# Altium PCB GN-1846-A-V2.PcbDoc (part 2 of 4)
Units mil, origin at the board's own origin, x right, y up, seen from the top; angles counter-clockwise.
Board outline 11624.17 x 2384.02 mil, 4 copper layers (Top, GND, VCC, Bottom), stack 40.7 mil thick; 450 components, 346 nets, 1652 pads, 832 vias.
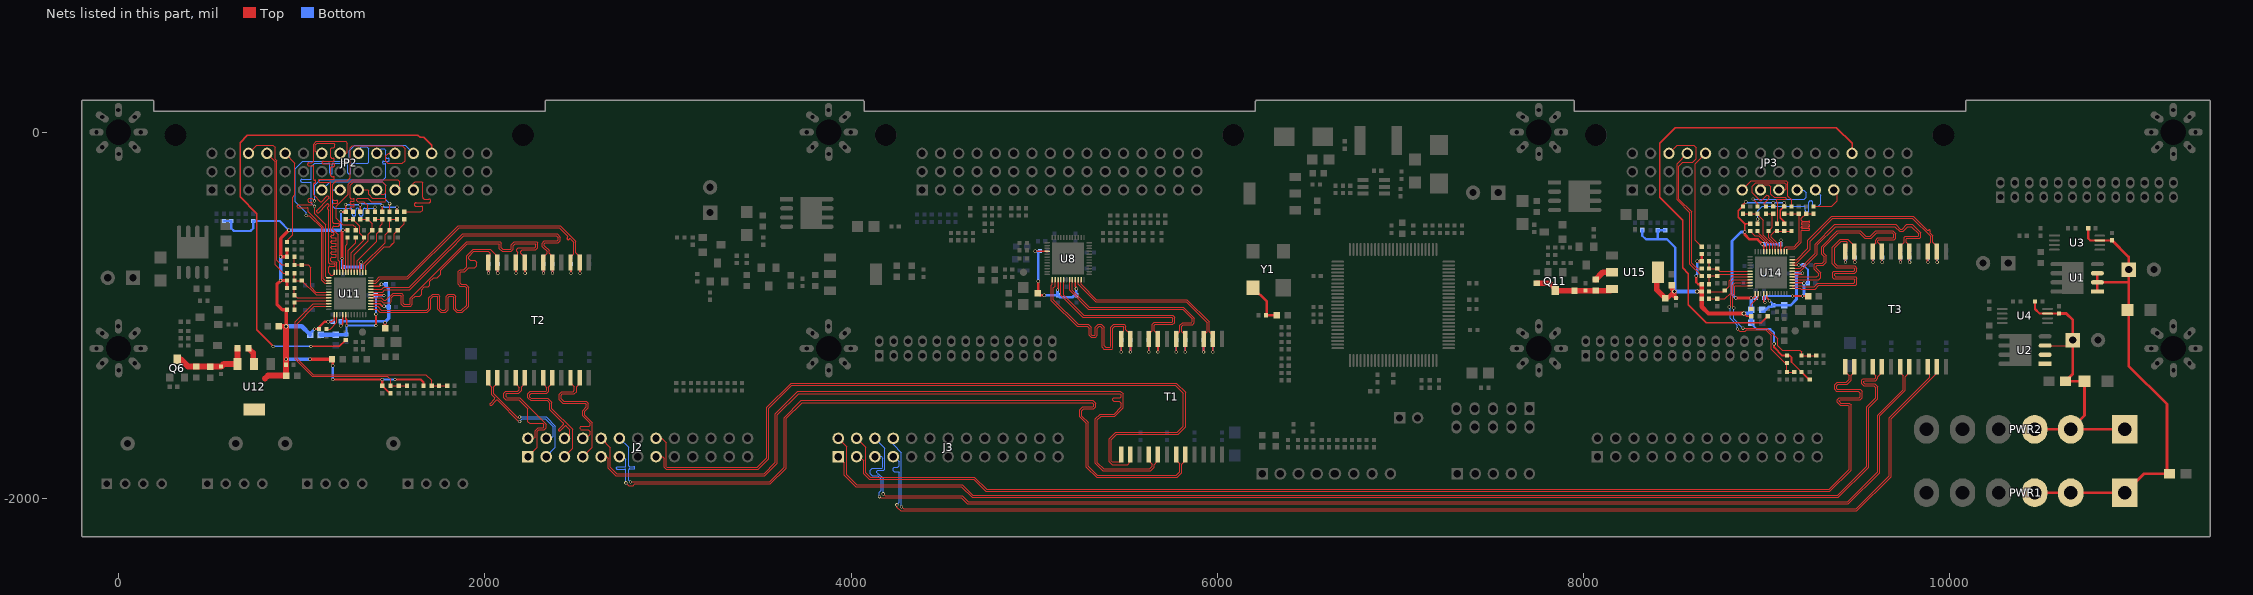
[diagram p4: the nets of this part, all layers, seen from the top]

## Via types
v1: diameter 18, hole 12, Top to Bottom, 768 vias
v2: diameter 24, hole 16, Top to Bottom, 34 vias
v3: diameter 30, hole 20, Top to Bottom, 27 vias
v4: diameter 40, hole 30, Top to Bottom, 2 vias
v5: diameter 24, hole 14, Top to Bottom, 1 vias

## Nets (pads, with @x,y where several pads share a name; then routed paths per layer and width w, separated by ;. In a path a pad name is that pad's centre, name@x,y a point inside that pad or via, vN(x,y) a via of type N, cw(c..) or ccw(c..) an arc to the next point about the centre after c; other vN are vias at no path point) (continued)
A_MX2_N: J2.12 T1.19 | length 4235.9
  Top w6: v1(2795,-1910) 3555,-1910 3635,-1830 3635,-1558 3728,-1465 5320,-1465 5335,-1480 5335,-1500 5325,-1510 5270,-1510 5260,-1520 5260,-1550 5295,-1585 5295,-1824.44 5344.56,-1874 5775,-1874 5795,-1854 5795,-1810 T1.19@5775,-1790
  Bottom w6: J2.12@2735,-1671.65 2785,-1721.65 2785,-1820.6 ccw(c2790.4,-1820.6) 2790.4,-1826 2813.98,-1826 cw(c2813.98,-1831.4) 2819.38,-1831.4 2819.38,-1832.6 cw(c2813.98,-1832.6) 2813.98,-1838 2790.4,-1838 ccw(c2790.4,-1843.4) 2785,-1843.4 2785,-1900 v1(2795,-1910)
A_MX2_P: J2.11 T1.20 | length 4225.8
  Top w6: v1(2770,-1915) 2785,-1930 2810,-1930 2819,-1921 3559.56,-1921 3646,-1834.56 3646,-1562.56 3732.56,-1476 5315.44,-1476 5324,-1484.56 5324,-1495.44 5320.44,-1499 5265.44,-1499 5249,-1515.44 5249,-1554.56 5284,-1589.56 5284,-1829 5340,-1885 5779.56,-1885 5806,-1858.56 5806,-1814 T1.20@5825,-1795
  Bottom w6: J2.11@2735,-1771.65 2756.65,-1771.65 2770,-1785 2770,-1822.6 cw(c2764.6,-1822.6) 2764.6,-1828 2723.6,-1828 ccw(c2723.6,-1833.4) 2718.2,-1833.4 2718.2,-1834.6 ccw(c2723.6,-1834.6) 2723.6,-1840 2764.6,-1840 cw(c2764.6,-1845.4) 2770,-1845.4 v1(2770,-1915)
A_MX3_N: J2.10 T1.16 | length 4210.2
  Top w6: J2.10@2635,-1671.65 2685.91,-1722.56 2685.91,-1830.35 2720.56,-1865 3525,-1865 3587,-1803 3587,-1538 3710,-1415 5470.56,-1415 5485,-1429.44 5485,-1505 5440,-1550 5365,-1550 5345,-1570 5345,-1804.44 5379.56,-1839 5630.28,-1839 5644.28,-1825 5644.28,-1814.28 5625,-1795 T1.16@5625,-1759.96
A_MX3_P: J2.9 T1.17 | length 4202.5
  Top w6: J2.9@2635,-1771.65 2665.65,-1771.65 2674,-1780 2674,-1834 2716,-1876 3529.56,-1876 3598,-1807.56 3598,-1542.56 3712.78,-1427.78 5467.78,-1427.78 5474,-1434 5474,-1445 5469,-1450 5435,-1450 5430,-1455 5430,-1465 5435,-1470 5465,-1470 5474,-1479 5474,-1500.44 5435.56,-1538.89 ; 5435.44,-1539 5360.44,-1539 5334,-1565.44 5334,-1809 5375,-1850 5634.83,-1850 5655.28,-1829.56 5655.28,-1814.72 5675,-1795 T1.17@5675,-1790
A_MX4_N: J2.16 T1.13 | length 4227.9
  Top w6: J2.16@2935,-1671.65 2966.65,-1671.65 2991,-1696 2991,-1826 2995,-1830 3488,-1830 3540,-1778 3540,-1502 3672,-1370 5775.56,-1370 5826,-1420.44 5826,-1609.56 5785.56,-1650 5450.4,-1650 5421,-1679.4 5421,-1795.44 5425.56,-1800 5470,-1800 5475,-1795 T1.13@5475,-1769.96
A_MX4_P: J2.15 T1.14 | length 4235
  Top w6: J2.15@2935,-1771.65 2971.65,-1771.65 2980,-1780 2980,-1830.56 2990.44,-1841 3492.56,-1841 3551,-1782.56 3551,-1506.56 3676.56,-1381 5771,-1381 5815,-1425 5815,-1605 5781,-1639 5445.84,-1639 5410,-1674.84 5410,-1800 5425,-1815 5510,-1815 5525,-1800 T1.14@5525,-1769.96
  Top w8: T1.14@5526.14,-1770.8 T1.14@5526.14,-1741.14
A_TD1_N: C52.2 T1.3 U8.10 | length 1102.9
  Top w6: U8.10@5240.12,-804.96 5240.12,-830.12 5335,-925 5829.44,-925 5944.72,-1040.28 5944.72,-1090.28 5926.14,-1108.86 5926.14,-1140.88 5926.14,-1190.88
  Top w8: T1.3@5926.14,-1140.88 T1.3@5928.15,-1142.89
  Top w10: v1(5925,-1200) T1.3@5925,-1140.04
  Bottom w10: v1(5925,-1200) C52.2@5925,-1135
A_TD1_P: C53.2 T1.2 U8.11 | length 1054
  Top w6: U8.11@5255.87,-804.96 5255.87,-830.31 5339.56,-914 5834,-914 5955.72,-1035.72 5955.72,-1090.72 5976.14,-1111.14 T1.2@5976.14,-1140.88
  Top w8: T1.2@5976.14,-1140.88 T1.2@5978.15,-1142.89 ; T1.2@5976.14,-1111.14 T1.2@5976.14,-1108.83
  Top w10: v1(5975,-1200) T1.2@5975,-1140.04
  Bottom w10: v1(5975,-1200) C53.2@5975,-1135
A_TD2_N: C51.2 T1.6 U8.7 | length 1105.6
  Top w6: U8.7@5192.87,-804.96 5192.87,-863.43 5295.44,-966 5810.44,-966 5864,-1019.56 5864,-1036 5860,-1040 5810.44,-1040 5795,-1055.44 5795,-1090 T1.6@5775,-1110
  Top w10: v1(5775,-1200) T1.6@5775,-1110
  Bottom w10: v1(5775,-1200) C51.2@5775,-1135
A_TD2_P: C46.2 T1.5 U8.8 | length 1104.8
  Top w6: U8.8@5208.62,-804.96 5208.62,-863.62 5300,-955 5815,-955 5875,-1015 5875,-1040.56 5864.56,-1051 5815,-1051 5806,-1060 5806,-1091 T1.5@5825,-1110
  Top w10: v1(5825,-1200) T1.5@5825,-1110
  Bottom w6: v1(5825,-1200) v1@5826.14,-1201.14
  Bottom w10: v1(5825,-1200) C46.2@5825,-1135
A_TD3_N: C45.2 T1.9 U8.4 | length 1111.5
  Top w6: U8.4@5145.63,-804.96 5145.63,-891.19 5265.44,-1011 5751,-1011 5755,-1015 5755,-1035 5751,-1039 5655.44,-1039 5645,-1049.44 5645,-1085 T1.9@5626.14,-1103.86 ; T1.9@5625,-1105 T1.9@5626.14,-1103.86 ; T1.9@5626.14,-1140.88 T1.9@5626.14,-1103.86
  Top w8: T1.9@5626.14,-1140.88 T1.9@5628.15,-1142.89
  Top w10: v1(5625,-1200) T1.9@5625,-1140.04
  Bottom w10: v1(5625,-1200) C45.2@5625,-1135
A_TD3_P: C50.2 T1.8 U8.5 | length 1104.3
  Top w6: U8.5@5161.38,-804.96 5161.38,-891.38 5270,-1000 5755.56,-1000 5766,-1010.44 5766,-1039.56 5755.56,-1050 5660,-1050 5656,-1054 5656,-1085 T1.8@5675,-1104
  Top w10: v1(5675,-1200) T1.8@5675,-1104
  Bottom w10: v1(5675,-1200) C50.2@5675,-1135
A_TD4_N: C48.2 T1.12 U8.1 | length 1092.7
  Top w6: U8.1@5098.39,-804.96 5098.39,-831.61 5094,-836 5094,-919.56 5235.44,-1061 5290,-1061 5300,-1071 5300,-1110 5310,-1120 5335,-1120 5345,-1110 5345,-1070 5354,-1061 5361,-1061 5370,-1070 5370,-1175 5380,-1185 5425,-1185 5430,-1180 5430,-1070 5439,-1061 5486,-1061 5490,-1065 5490,-1085 5475,-1100 T1.12@5475,-1130.04
  Top w10: v1(5475,-1200) T1.12@5475,-1140.04
  Bottom w10: v1(5475,-1200) C48.2@5475,-1135
A_TD4_P: C49.2 T1.11 U8.2 | length 1103
  Top w6: U8.2@5114.13,-804.96 5114.13,-840.87 5105,-850 5105,-915 5240,-1050 5294.56,-1050 5311,-1066.44 5311,-1105 5315,-1109 5330.44,-1109 5334,-1105.44 5334,-1065.44 5349.44,-1050 5365.56,-1050 5381,-1065.44 5381,-1165 5390,-1174 5415,-1174 5419,-1170 5419,-1065.44 5434.44,-1050 5490.56,-1050 5501,-1060.44 5501,-1080 5525,-1104 T1.11@5525,-1130.04
  Top w8: T1.11@5526.14,-1130.04 T1.11@5526.14,-1118.83
  Top w10: v1(5525,-1200) T1.11@5525,-1140.04
  Bottom w10: v1(5525,-1200) C49.2@5525,-1135
APHY105: B4.1 C35.1 C36.1 C37.1 U8.3 U8.9 U8.40 | length 711.2
  Top w8: v1(5126.85,-861.48) 5129.88,-858.45 5129.88,-848.45 U8.3@5129.88,-804.96 ; U8.9@5224.37,-804.96 5224.37,-841.68 5230,-847.31 v1(5230,-855)
  Top w10: v1(5005,-650) 5069.41,-650 U8.40@5070.04,-650.63
  Top w15: B4.1@5020,-880.47 B4.1@5021.85,-878.62 ; v1(5021.85,-814.16) B4.1@5021.85,-878.62 ; v1(5055,-890) 5033.23,-890 B4.1@5021.85,-878.62
  Bottom w12: v1(5005,-650) 5021.85,-650 v1(5021.85,-814.16)
  Bottom w15: v1(5055,-890) C37.1@5130,-890 ; v1(5126.85,-861.48) 5126.85,-886.85 C37.1@5130,-890 ; v1(5230,-855) C36.1@5230,-890 ; C36.1@5230.84,-889.16 C36.1@5230,-890 ; C37.1@5130,-890 5140.66,-900.66 5209.34,-900.66 5220,-890 C36.1@5230,-890
B3V3A: B8.1 C75.1 C76.1 C77.1 U11.6 U11.41 | length 693.8
  Top w8: U11.41@1239.53,-995.8 1239.53,-1020 1245,-1025.47 v1(1245,-1055)
  Top w10: U11.6@1378.11,-888.71 1449.53,-888.71 v1(1449.53,-891.58)
  Top w12: v1(1405,-1055) v1(1405,-993.71)
  Bottom w12: C76.1@1245,-1095.47 v1(1245,-1055) v1(1405,-1055) ; v1(1405,-993.71) C75.1@1405,-891.58 ; v1(1449.53,-891.58) C75.1@1405,-891.58 ; C75.1@1405,-891.58 1404.53,-891.58 C75.1@1404.53,-890 1405,-890 C75.1@1405,-891.58
  Bottom w18: C77.1@1169.53,-1105.47 C76.1@1245,-1105.47
  Bottom w24: B8.1@1104.53,-1105 C77.1@1174.53,-1105
B3V3D: B6.2 B8.2 C65.1 C66.1 C67.1 C68.1 C89.1 C90.1 R94.1 R97.1 R102.1 R106.2 R107.1 R108.2 R110.2 R112.2 R113.2 R114.2 R119.2 R123.2 R124.2 R128.2 R131.2 R412.2 R413.2 R414.2 U11.15 U11.21 U11.37 U12.2 U12.4 | length 4425.3
  Top w8: v1(1145,-1035) 1165,-1035 1176.54,-1023.46 U11.37@1176.54,-995.8 ; U11.21@1223.78,-765.88 v1@1223.78,-693.78 ; R131.2@1240,-435 v1(1240,-395) ; U11.15@1318.27,-765.88 1318.27,-716.73 v1(1325,-710) ; R128.2@1320,-435 v1(1320,-396.5) ; R124.2@1440,-435 v1(1440,-400) ; R119.2@1520,-435 v1(1520,-410)
  Top w10: v1@1220,-540 v1(1225,-535) R106.2@1250,-535 ; R102.1@1440,-1385 R112.2@1480,-1425
  Top w12: v1(1070,-1075) R108.2@1095,-1075 1095,-1065 1125,-1035 v1(1145,-1035) ; B6.2@1165.47,-1240 1170,-1244.53 v1(1170,-1275) ; v1@1175,-1350 v1(1440,-1350) R102.1@1440,-1385 ; v1(1215,-435) R131.2@1240,-435 ; v1(1510,-1350) 1650,-1350 1665,-1365 R97.1@1665,-1385
  Top w15: v1(1220,-690) v1@1220,-540
  Top w18: v2(915,-1060) 915,-975 R110.2@920,-970 895,-970 865,-940 865,-830 v1(885,-810) R114.2@920,-810 R123.2@920,-850 ; R94.1@920,-640 R113.2@920,-680 v1(885,-680) 885,-580 v1(930,-535) ; v1(1045,-1240) B6.2@1165.47,-1240
  Top w24: C90.1@874.53,-1060 v2(915,-1060)
  Top w30: R107.1@710,-1180 735,-1205 U12.2@735,-1270
  Top w32: 800,-1345 815.47,-1329.53 915,-1329.53 C89.1@915,-1270 v1(915,-1240) v2(915,-1060)
  Bottom w8: v1(1240,-395) 1318.5,-395 v1(1320,-396.5) 1324.5,-392 1432,-392 v1(1440,-400) 1450,-410 v1(1520,-410) ; C66.1@1324.53,-735.47 C66.1@1325,-735 v1(1325,-710)
  Bottom w12: R414.2@575,-485 R413.2@615,-485 615,-525 630,-540 720,-540 735,-525 R412.2@735,-485 880,-485 v1(930,-535) ; B8.2@1045.47,-1105 1045.47,-1099.53 v1(1070,-1075) ; v1(1145,-1035) C65.1@1170,-1035 ; v1(1170,-1350) v1(1170,-1275) ; v1(1215,-435) 1215,-525 v1(1225,-535) ; v1(1220,-690) 1220,-730.47 C67.1@1225,-735.47 ; v1(1440,-1350) v1(1510,-1350)
  Bottom w15: C67.1@1225,-735.47 C66.1@1324.53,-735.47
  Bottom w18: v1(885,-810) v1(885,-680) ; v1(915,-1240) v1(1045,-1240) ; v1(930,-535) v1(1225,-535)
  Bottom w24: v2(915,-1060) 1000.47,-1060 B8.2@1045.47,-1105
B5V: C91.1 C92.1 Q6.3 R107.2 R109.1 U12.3 | length 437.2
  Top w32: Q6.3@320,-1240 340,-1240 380,-1280 C91.1@560,-1280 575,-1265 U12.3@649,-1265 649,-1181 R107.2@650,-1180
B_MCLK: JP2.A3 R120.1 | length 855.9
  Top w5: JP2.A3@709.84,-115.13 754.97,-70 842.31,-70 855,-82.69 855,-146.54 865,-156.54 865,-700 890,-725 R120.1@920,-725
B_MDIO: JP2.A4 R122.1 | length 711.8
  Top w5: JP2.A4@809.84,-115.52 855,-160.68 855,-725 900,-770 R122.1@920,-770
B_MX1_N: J2.8 T2.22 | length 693.3
  Top w6: T2.22@2468.15,-1340.8 2468.15,-1368.15 2489.09,-1389.09 2489.09,-1410 2481.49,-1417.6 2419.4,-1417.6 2405,-1432 2405,-1460 2425,-1480 2549.44,-1480 2554,-1484.56 2554,-1500.44 2534,-1520.44 2534,-1549.56 2575,-1590.56 2575,-1600 2570,-1605 2525,-1605 2520,-1610 2520,-1620 2525,-1625 2565,-1625 2575,-1635 2575,-1650 2553.35,-1671.65 J2.8@2535,-1671.65
B_MX1_P: J2.7 T2.23 | length 691.9
  Top w6: T2.23@2518.15,-1340.8 2518.15,-1371.85 2501,-1389 2501,-1416 2488.4,-1428.6 2423.96,-1428.6 2416,-1436.56 2416,-1455.44 2429.56,-1469 2554,-1469 2565,-1480 2565,-1505 2545,-1525 2545,-1545 2586,-1586 2586,-1720.65 J2.7@2535,-1771.65
B_MX2_N: J2.6 T2.19 | length 688.3
  Top w6: T2.19@2318.15,-1340.8 2325,-1347.65 2325,-1380 2339.28,-1394.28 2339.28,-1410 2334.28,-1415 2248,-1415 2235,-1428 2235,-1450.56 2249.44,-1465 2340,-1465 2355,-1480 2355,-1515 2428.75,-1588.75 cw(c2424.94,-1592.57) 2428.75,-1596.39 2403.59,-1621.56 ccw(c2407.4,-1625.38) 2403.59,-1629.2 2404.43,-1630.04 ccw(c2408.25,-1626.23) 2412.07,-1630.04 2437.24,-1604.88 cw(c2441.06,-1608.69) 2444.88,-1604.88 2465,-1625 2465,-1660 2453.35,-1671.65 J2.6@2435,-1671.65
B_MX2_P: J2.5 T2.20 | length 700.6
  Top w6: T2.20@2368.15,-1340.8 2360,-1348.95 2360,-1380 2350.28,-1389.72 2350.28,-1414.56 2338.83,-1426 2252.56,-1426 2246,-1432.56 2246,-1446 2254,-1454 2344.56,-1454 2366,-1475.44 2366,-1509.16 2480,-1623.16 2480,-1726.65 J2.5@2435,-1771.65
B_MX3_N: J2.2 T2.16 | length 685.8
  Top w6: T2.16@2168.15,-1368.15 T2.16@2168.15,-1340.8 2175,-1347.65 2175,-1380 2189.09,-1394.09 2189.09,-1405.91 2180,-1415 2115,-1415 2104,-1426 2104,-1449 2115,-1460 2185,-1460 2235,-1510 2235,-1580 2245,-1590 2315,-1590 2322.5,-1597.5 2322.5,-1611.5 2320,-1614 2290.44,-1614 2275,-1629.44 2275,-1665 2268.35,-1671.65 J2.2@2235,-1671.65
B_MX3_P: J2.1 T2.17 | length 701.7
  Top w6: T2.17@2218.15,-1340.8 2218.15,-1371.85 2201,-1389 2201,-1409.56 2184.56,-1426 2119.56,-1426 2116,-1429.56 2116,-1445 2120,-1449 2189.56,-1449 2335,-1594.44 2335,-1615 2325,-1625 2295,-1625 2286,-1634 2286,-1720.65 J2.1@2235,-1771.65
B_MX4_N: J2.4 T2.13 | length 703.1
  Top w6: T2.13@2018.15,-1340.8 2018.15,-1373.15 2039,-1394 2039,-1434 2053.93,-1448.93 cw(c2050.11,-1452.75) 2053.93,-1456.56 2028.21,-1482.28 ccw(c2032.03,-1486.1) 2028.21,-1489.92 2029.06,-1490.76 ccw(c2032.88,-1486.95) 2036.7,-1490.76 2062.41,-1465.05 cw(c2066.23,-1468.87) 2070.05,-1465.05 2187.5,-1582.5 v1@2190,-1585
  Bottom w6: v1(2190,-1580) 2204,-1566 2330.44,-1566 2374,-1609.56 2374,-1661 2363.35,-1671.65 J2.4@2335,-1671.65
B_MX4_P: J2.3 T2.14 | length 699.8
  Top w6: 2050,-1399.44 2050,-1395 ; T2.14@2068.15,-1340.8 2068.15,-1371.85 2050,-1390 2050,-1395 ; v1(2190,-1555) 2185,-1560 2180.56,-1560 2050,-1429.44 2050,-1395
  Bottom w6: v1(2190,-1555) 2335,-1555 2385,-1605 2385,-1721.65 J2.3@2335,-1771.65
B_TD1_N: C85.2 T2.3 U11.10 | length 1512
  Top w6: U11.10@1378.11,-825.72 1403.27,-825.72 1427.99,-801 1579.56,-801 1859.56,-521 2406,-521 2452.17,-567.17 cw(c2448.35,-570.98) 2452.17,-574.8 2450,-576.97 ccw(c2453.82,-580.79) 2450,-584.61 2450.85,-585.45 ccw(c2454.67,-581.64) 2458.49,-585.45 2460.65,-583.29 cw(c2464.47,-587.11) 2468.29,-583.29 2485,-600 2485,-663.15 T2.3@2468.15,-680
  Top w8: T2.3@2468.15,-680 T2.3@2468.15,-710.88 T2.3@2470,-712.73
  Top w10: v1(2470,-770) T2.3@2470,-712.73
  Bottom w10: v1(2470,-770) C85.2@2470,-720
B_TD1_P: C80.2 T2.2 U11.11 | length 1512
  Top w6: U11.11@1378.11,-809.97 1403.46,-809.97 1423.43,-790 1575,-790 1855,-510 2410.56,-510 2496,-595.44 2496,-657.85 T2.2@2518.15,-680
  Top w8: T2.2@2518.15,-680 T2.2@2518.15,-710.88 T2.2@2520,-712.73
  Top w10: v1(2520,-770) T2.2@2520,-712.73
  Bottom w10: v1(2520,-770) C80.2@2520,-720
B_TD2_N: C83.2 T2.6 U11.7 | length 1494
  Top w6: U11.7@1378.11,-872.97 1442.03,-872.97 1454,-861 1589,-861 1592.03,-857.97 1809,-641 ; 1810,-641 1885,-566 2390,-566 2401,-577 2401,-588 2395,-594 2325.44,-594 2314,-605.44 2314,-624.56 2340,-650.56 2340,-660 T2.6@2318.15,-681.85
  Top w8: T2.6@2318.15,-681.85 T2.6@2318.15,-710.88 T2.6@2320,-712.73
  Top w10: v1(2320,-770) T2.6@2320,-712.73
  Bottom w10: v1(2320,-770) C83.2@2320,-720
B_TD2_P: C84.2 T2.5 U11.8 | length 1510.8
  Top w6: U11.8@1378.11,-857.22 1437.78,-857.22 1448.03,-846.97 1587.47,-846.97 1879.44,-555 2394.56,-555 2412,-572.44 2412,-592.56 2399.56,-605 2330,-605 2325,-610 2325,-620 2351,-646 2351,-661 T2.5@2370,-680
  Top w8: T2.5@2370,-712.73 T2.5@2368.15,-710.88 2370,-709.03 T2.5@2370,-680
  Top w10: v1(2370,-770) T2.5@2370,-712.73
  Bottom w10: v1(2370,-770) C84.2@2370,-720
B_TD3_N: C79.2 T2.9 U11.4 | length 1515.2
  Top w6: U11.4@1378.11,-920.21 1434.65,-920.21 1444.44,-930 1485,-930 1490,-925 1490,-904.56 1503.56,-891 1540.44,-891 1544,-894.56 1544,-939 1555,-950 1595,-950 1604.77,-940.23 ; 1605,-940 1605,-910 1620,-895 1645,-895 1655,-885 1655,-860 1670,-845 1690,-845 1700,-835 1700,-815 1720,-795 1740,-795 1760,-775 1760,-755 1905,-610 2075,-610 2080,-615 2080,-635.56 2094.44,-650 2145,-650 2155,-640 2155,-620 2165,-610 2274,-610 2279,-615 2279,-625.44 2272.8,-631.64 2183.36,-631.64 2175,-640 2175,-650 2180,-655 2180,-670 T2.9@2168.15,-681.85
  Top w10: v1(2170,-770) T2.9@2170,-712.73
  Bottom w10: v1(2170,-770) C79.2@2170,-720
B_TD3_P: C82.2 T2.8 U11.5 | length 1511.6
  Top w6: U11.5@1378.11,-904.46 1434.46,-904.46 1449,-919 1460,-919 1499,-880 1545,-880 1555,-890 1555,-934 1560,-939 1590.44,-939 1594,-935.44 1594,-905.44 1900.44,-599 2084.56,-599 2091,-605.44 2091,-631 2099,-639 2140.44,-639 2144,-635.44 2144,-615.44 2161.35,-598.09 2283.09,-598.09 2290,-605 2290,-630 2277.36,-642.64 2204.6,-642.64 2197.24,-650 ; 2197.64,-650 2197.24,-650 ; T2.8@2218.15,-683.15 2197.24,-662.24 2197.24,-650
  Top w8: T2.8@2218.15,-683.15 T2.8@2218.15,-710.88 T2.8@2220,-712.73
  Top w10: v1(2220,-770) T2.8@2220,-712.73
  Bottom w10: v1(2220,-770) C82.2@2220,-720
B_TD4_N: C81.2 T2.12 U11.1 | length 1522.7
  Top w6: U11.1@1378.11,-967.45 1408.7,-967.45 1425.25,-984 1686.56,-984 1706,-964.56 1706,-909.56 1719.56,-896 1740.44,-896 1744,-899.56 1744,-967.56 1760.44,-984 1786.56,-984 1801,-969.56 1801,-900 1805,-896 1825,-896 1829,-900 1829,-967.56 1845.44,-984 1876.56,-984 1910.91,-949.65 1910.91,-845.44 1894.46,-829 1870,-829 1866,-825 1866,-764.56 1869.56,-761 1889.46,-761 1910.91,-739.56 1945,-739.56 1955,-729.56 1955,-710 1945,-700 1920,-700 1910.91,-690.91 1910.91,-679.09 1940,-650 2020,-650 2030,-660 2030,-683.15
  Top w10: v1(2020,-770) T2.12@2020,-712.73
  Bottom w10: v1(2020,-770) C81.2@2020,-720
B_TD4_P: C78.2 T2.11 U11.2 | length 1517
  Top w6: U11.2@1378.11,-951.71 1414.09,-951.71 1435.38,-973 1682,-973 1695,-960 1695,-905 1715,-885 1745,-885 1755,-895 1755,-963 1765,-973 1782,-973 1790,-965 1790,-895 1800,-885 1829.56,-885 1840,-895.44 1840,-963 1850,-973 1872,-973 1899.91,-945.09 1899.91,-850 1889.91,-840 1864,-840 1855,-831 1855,-760 1865,-750 1884.91,-750 1899.91,-735 1899.91,-674.54 1935.44,-639 2029,-639 2068.15,-678.15 T2.11@2068.15,-710.88
  Top w8: T2.11@2068.15,-710.88 T2.11@2070,-712.73
  Top w10: v1(2070,-770) T2.11@2070,-712.73
  Bottom w10: v1(2070,-770) C78.2@2070,-720
BEPHY_CLK: JP2.A13 R96.1 | length 2753.3
  Top w8: v1(845,-1170) 755,-1080 755,-445 663.15,-353.15 663.15,-56.39 704.04,-15.5 1633.27,-15.5 1646.2,-28.44 1665.75,-28.44 1709.84,-72.53 JP2.A13@1709.84,-115.13 ; v1(1050,-1170) 1205,-1170 R96.1@1240,-1135
  Bottom w8: v1(845,-1170) 890,-1170 ; 915,-1170 890,-1170 ; v1(1050,-1170) 890,-1170
BEPHY_RSTN: JP2.A5 R95.1 | length 524.8
  Top w5: JP2.A5@909.84,-115.13 963.15,-168.44 963.15,-340.85 950,-354 950,-560 920,-590 R95.1@920,-600
BGE0_ENREG: R108.1 U11.38 | length 115.1
  Top w5: R108.1@1135,-1075 1155.86,-1075 1192.28,-1038.58 U11.38@1192.28,-995.8
BGE0_INT_N: R106.1 U11.20 | length 195.2
  Top w5: U11.20@1239.53,-765.88 1239.53,-619.47 1250,-609 R106.1@1250,-575
BGE0_LED0: R103.1 R104.1 R112.1 U11.34 | length 1119.8
  Top w5: U11.34@1148.19,-935.96 1064.04,-935.96 965,-1035 965,-1240 1058.5,-1333.5 1468.5,-1333.5 1485,-1350 R112.1@1485,-1385 R104.1@1575,-1385
BGE0_LED1: R98.1 R99.1 R115.1 U11.35 | length 1302
  Top w5: U11.35@1148.19,-951.71 1068.29,-951.71 975,-1045 975,-1235.86 1062.64,-1323.5 1678.5,-1323.5 1710,-1355 R98.1@1710,-1385 R99.1@1795,-1385
BGE0_LED2: R123.1 R125.1 U11.32 | length 234.2
  Top w5: R123.1@960,-850 R125.1@960,-890 974.46,-904.46 U11.32@1148.19,-904.46
BGE0_PME: R110.1 R111.1 U11.33 | length 232.2
  Top w5: R110.1@960,-970 R111.1@960,-930 969.79,-920.21 U11.33@1148.19,-920.21
BGE0_RXCLK: R87.2 U11.19 | length 207.3
  Top w5: U11.19@1255.28,-765.88 1255.28,-644.72 1295,-605 R87.2@1295,-575
BGE0_RXCTL: R88.2 R116.1 U11.13 | length 421.3
  Top w5: U11.13@1349.76,-765.88 1349.76,-725.24 1449.92,-625.08 1479.92,-625.08 ; 1498.15,-606.85 1479.92,-625.08 ; R88.2@1560,-475 1560,-500 R116.1@1525,-535 1505,-555 1505,-600 1479.92,-625.08
BGE0_RXD0: R89.2 R119.1 R121.1 U11.14 | length 391.3
  Top w5: U11.14@1334.02,-765.88 1334.02,-724.31 1455,-603.33 1455,-560 R121.1@1480,-535 R89.2@1480,-475 R119.1@1520,-475
BGE0_RXD1: R90.2 R124.1 R126.1 U11.16 | length 387.8
  Top w5: U11.16@1302.52,-765.88 1302.52,-702.48 1410,-595 1410,-555 R126.1@1430,-535 1430,-510 1440,-500 R124.1@1440,-475 R90.2@1400,-475
BGE0_RXD2: R91.2 R128.1 R130.1 U11.17 | length 381.9
  Top w5: U11.17@1286.77,-765.88 1286.77,-670.23 1363,-594 1363,-557 R130.1@1385,-535 1385,-500 R91.2@1360,-475 R128.1@1320,-475
BGE0_RXD3: R93.2 R131.1 R132.1 U11.18 | length 384.3
  Top w5: R131.1@1240,-475 R93.2@1280,-475 1318,-513 1318,-553 R132.1@1340,-575 1340,-590 1271.02,-658.98 U11.18@1271.02,-765.88
BMAC_MDC: C93.2 R113.1 R120.2 U11.30 | length 356
  Top w5: R113.1@960,-680 R120.2@960,-725 C93.2@1000,-725 1035,-725 1050,-740 1050,-845 1077.97,-872.97 U11.30@1148.19,-872.97
BMAC_MDIO: C94.2 R114.1 R122.2 U11.31 | length 260.8
  Top w5: R122.2@960,-770 R114.1@960,-810 C94.2@1000,-810 1078.71,-888.71 U11.31@1148.19,-888.71
BPHY105: B7.1 C69.1 C70.1 C71.1 U11.3 U11.9 U11.40 | length 770.2
  Top w8: v1(1213.6,-1056.4) 1223.78,-1046.22 U11.40@1223.78,-995.8 ; U11.3@1378.11,-935.96 1425.96,-935.96 1440,-950 v1(1450,-950) v1@1455,-950
  Top w10: U11.9@1378.11,-841.47 1423.53,-841.47 v1(1435,-830)
  Top w18: v1(1455,-1040) 1455,-1069.53 B7.1@1455.47,-1070
  Bottom w15: v1(1213.6,-1056.4) 1212.56,-1055.36 C69.1@1212.56,-1032.91 1447.91,-1032.91 ; v1(1435,-830) C71.1@1460,-830 1460,-840 1475,-855 C70.1@1475,-950 ; v1(1450,-950) C70.1@1470,-950
  Bottom w18: v1(1455,-1040) 1455,-1035.54 1475,-1015.54 C70.1@1475,-955 C70.1@1470,-950
BRGMII_RXCK: JP2.C11 R87.1 | length 703.1
  Top w5: R87.1@1295,-535 1295,-520 1280,-505 1225,-505 1190,-470 1190,-405 1255,-340 1255,-285 1280,-260 1525,-260 1535,-270 1535,-290.37 JP2.C11@1509.84,-315.52
BRGMII_RXD0: JP2.C7 R89.1 | length 530.6
  Top w5: R89.1@1480,-435 v1(1480,-390)
  Bottom w5: JP2.C7@1109.84,-315.52 1155.37,-270 1440,-270 1460,-290 1460,-370 v1(1480,-390)
BRGMII_RXD1: JP2.C8 R90.1 | length 525.6
  Top w5: R90.1@1400,-435 v1(1400,-410)
  Bottom w5: JP2.C8@1209.84,-315.52 1174.48,-315.52 1170,-320 1170,-405 1180,-415 1265,-415 cw(c1265,-425) 1275,-425 1275,-448 ccw(c1285,-448) 1285,-458 ccw(c1285,-448) 1295,-448 1295,-425 cw(c1305,-425) 1305,-415 cw(c1305,-425) 1315,-425 1315,-448 ccw(c1325,-448) 1325,-458 ccw(c1325,-448) 1335,-448 1335,-425 cw(c1345,-425) 1345,-415 1395,-415 v1(1400,-410)
BRGMII_RXD2: JP2.C9 R91.1 | length 480.1
  Top w5: JP2.C9@1309.84,-315.52 1360.52,-315.52 1365,-320 1365,-340 1385,-360 1455,-360 1460,-365 1460,-375 1455,-380 1380,-380 1360,-360 1305,-360 1300,-365 1300,-375 1305,-380 1340,-380 1360,-400 R91.1@1360,-435
BRGMII_RXD3: JP2.C10 R93.1 | length 541.2
  Top w5: R93.1@1280,-435 1265,-420 1265,-412.75 cw(c1270.25,-412.75) 1270.25,-407.5 1282.75,-407.5 ccw(c1282.75,-402.25) 1288,-402.25 1288,-397.75 ccw(c1282.75,-397.75) 1282.75,-392.5 1270.25,-392.5 cw(c1270.25,-387.25) 1265,-387.25 1265,-382.75 cw(c1270.25,-382.75) 1270.25,-377.5 1282.75,-377.5 ccw(c1282.75,-372.25) 1288,-372.25 1288,-367.75 ccw(c1282.75,-367.75) 1282.75,-362.5 1270.25,-362.5 cw(c1270.25,-357.25) 1265,-357.25 1265,-290 1285,-270 1440,-270 1460,-290 1460,-330 1450,-340 1434.32,-340 JP2.C10@1409.84,-315.52
BRGMII_RXDV: JP2.C12 R88.1 | length 502.3
  Top w5: R88.1@1560,-435 1650,-435 1660,-425 1660,-410 ccw(c1655,-410) 1655,-405 1625,-405 cw(c1625,-395) 1615,-395 cw(c1625,-395) 1625,-385 1695,-385 ccw(c1695,-375) 1705,-375 ccw(c1695,-375) 1695,-365 1670,-365 cw(c1670,-355) 1660,-355 1660,-275 1655,-270 1620,-270 1609.84,-280.16 JP2.C12@1609.84,-315.52
BRGMII_TXCKOUT: JP2.A11 U11.22 | length 1455.4
  Top w5: U11.22@1208.03,-765.88 1208.03,-708.03 1200,-700 1200,-560 1170,-530 1170,-517.75 cw(c1175.25,-517.75) 1175.25,-512.5 1201.19,-512.5 ccw(c1201.19,-507.25) 1206.44,-507.25 1206.44,-502.75 ccw(c1201.19,-502.75) 1201.19,-497.5 1175.25,-497.5 cw(c1175.25,-492.25) 1170,-492.25 1170,-392.75 cw(c1175.25,-392.75) 1175.25,-387.5 1191.19,-387.5 ccw(c1191.19,-382.25) 1196.44,-382.25 1196.44,-377.75 ccw(c1191.19,-377.75) 1191.19,-372.5 1175.25,-372.5 cw(c1175.25,-367.25) 1170,-367.25 1170,-285 1190,-265 1250,-265 1265,-250 1265,-85 1275,-75 1550,-75 1565,-90 1565,-155 1550,-170 1470,-170 1460,-160 1460,-130 1474.48,-115.52 JP2.A11@1509.84,-115.52
BRGMII_TXD0: JP2.A7 U11.23 | length 1465.2
  Top w5: JP2.A7@1109.84,-115.52 1085.52,-115.52 1075,-105 1075,-69.14 1084.14,-60 1175,-60 1180,-65 1180,-80 1175,-85 1165,-85 1160,-90 1160,-137.25 ccw(c1165.25,-137.25) 1165.25,-142.5 1173.27,-142.5 cw(c1173.27,-147.75) 1178.52,-147.75 1178.52,-152.25 cw(c1173.27,-152.25) 1173.27,-157.5 1118.24,-157.5 ccw(c1118.24,-162.75) 1112.99,-162.75 1112.99,-167.25 ccw(c1118.24,-167.25) 1118.24,-172.5 1174.22,-172.5 cw(c1174.22,-177.75) 1179.47,-177.75 1179.47,-182.25 cw(c1174.22,-182.25) 1174.22,-187.5 1165.25,-187.5 ccw(c1165.25,-192.75) 1160,-192.75 1160,-237.25 ccw(c1165.25,-237.25) 1165.25,-242.5 1173.27,-242.5 cw(c1173.27,-247.75) 1178.52,-247.75 1178.52,-252.25 cw(c1173.27,-252.25) 1173.27,-257.5 1096.52,-257.5 1093.4,-260.63 1093.4,-270.1 1095.79,-272.5 1154.75,-272.5 cw(c1154.75,-277.75) 1160,-277.75 1160,-542.25 ccw(c1165.25,-542.25) 1165.25,-547.5 1171.19,-547.5 cw(c1171.19,-552.75) 1176.44,-552.75 1176.44,-557.25 cw(c1171.19,-557.25) 1171.19,-562.5 1165.25,-562.5 ccw(c1165.25,-567.75) 1160,-567.75 1160,-572.25 ccw(c1165.25,-572.25) 1165.25,-577.5 1184.75,-577.5 cw(c1184.75,-582.75) 1190,-582.75 1190,-587.25 cw(c1184.75,-587.25) 1184.75,-592.5 1165.25,-592.5 ccw(c1165.25,-597.75) 1160,-597.75 1160,-602.25 ccw(c1165.25,-602.25) 1165.25,-607.5 1184.75,-607.5 cw(c1184.75,-612.75) 1190,-612.75 1190,-617.25 cw(c1184.75,-617.25) 1184.75,-622.5 1165.25,-622.5 ccw(c1165.25,-627.75) 1160,-627.75 1160,-632.25 ccw(c1165.25,-632.25) 1165.25,-637.5 1184.75,-637.5 cw(c1184.75,-642.75) 1190,-642.75 1190,-647.25 cw(c1184.75,-647.25) 1184.75,-652.5 1165.25,-652.5 ccw(c1165.25,-657.75) 1160,-657.75 1160,-662.25 ccw(c1165.25,-662.25) 1165.25,-667.5 1184.75,-667.5 cw(c1184.75,-672.75) 1190,-672.75 1190,-677.25 cw(c1184.75,-677.25) 1184.75,-682.5 1165.25,-682.5 ccw(c1165.25,-687.75) 1160,-687.75 1160,-702.5 1164.18,-706.68 1186.68,-706.68 1192.28,-712.28 U11.23@1192.28,-765.88
BRGMII_TXD1: JP2.A8 U11.24 | length 1432.9
  Top w5: 1084.72,-438.82 1081.54,-435.63 cw(c1085.25,-431.92) 1081.53,-428.22 1148.46,-361.28 ccw(c1144.75,-357.57) 1148.47,-353.87 1145.28,-350.68 ; 1084.73,-438.83 ccw(c1088.43,-435.1) 1092.13,-438.83 ; 1092.14,-438.82 1137.86,-393.1 cw(c1141.57,-396.81) 1145.27,-393.09 ; 1137.86,-350.68 1109.65,-378.88 cw(c1105.94,-375.17) 1102.23,-378.89 1065,-341.66 1065,-282.75 cw(c1070.25,-282.75) 1070.25,-277.5 1072.75,-277.5 ccw(c1072.75,-272.25) 1078,-272.25 1078,-267.75 ccw(c1072.75,-267.75) 1072.75,-262.5 1070.25,-262.5 cw(c1070.25,-257.25) 1065,-257.25 1065,-185 ccw(c1062.5,-185) 1062.5,-182.5 1037.25,-182.5 cw(c1037.25,-177.25) 1032,-177.25 1032,-172.75 cw(c1037.25,-172.75) 1037.25,-167.5 1055,-167.5 1065,-157.5 1065,-65 1080,-50 1240,-50 1250,-60 1250,-110 1244.48,-115.52 JP2.A8@1209.84,-115.52 ; 1137.87,-350.67 cw(c1141.57,-354.39) 1145.27,-350.67 ; 1141.47,-418.13 1148.34,-425 1148.34,-712.25 ccw(c1153.59,-712.25) 1153.59,-717.5 1177.03,-717.5 cw(c1177.03,-722.75) 1182.28,-722.75 1182.28,-727.25 cw(c1177.03,-727.25) 1177.03,-732.5 1153.59,-732.5 ccw(c1153.59,-737.75) 1148.34,-737.75 1148.34,-768.34 1160,-780 1170,-780 1176.54,-773.46 U11.24@1176.54,-765.88 ; 1141.46,-418.12 cw(c1145.18,-414.42) 1141.46,-410.71 1148.46,-403.71 ccw(c1144.75,-400) 1148.47,-396.29 1145.28,-393.1
BRGMII_TXD2: JP2.A9 U11.25 | length 1458.2
  Top w5: v1(1070,-405) 1070,-445 1130.39,-505.39 1130.39,-789.61 1135,-794.23 U11.25@1148.19,-794.23
  Bottom w5: v1(1070,-405) 1053.5,-388.5 1053.5,-277.75 ccw(c1048.25,-277.75) 1048.25,-272.5 1000.75,-272.5 cw(c1000.75,-267.25) 995.5,-267.25 995.5,-262.75 cw(c1000.75,-262.75) 1000.75,-257.5 1051,-257.5 ccw(c1051,-255) 1053.5,-255 1053.5,-186.5 1070,-170 1147.25,-170 cw(c1147.25,-175.25) 1152.5,-175.25 1152.5,-222.75 ccw(c1157.75,-222.75) 1157.75,-228 1162.25,-228 ccw(c1162.25,-222.75) 1167.5,-222.75 1167.5,-175.25 cw(c1172.75,-175.25) 1172.75,-170 1247.25,-170 cw(c1247.25,-175.25) 1252.5,-175.25 1252.5,-222.75 ccw(c1257.75,-222.75) 1257.75,-228 1262.25,-228 ccw(c1262.25,-222.75) 1267.5,-222.75 1267.5,-175.25 cw(c1272.75,-175.25) 1272.75,-170 1360,-170 1365,-165 1365,-90 1355,-80 1325,-80 1309.84,-95.16 JP2.A9@1309.84,-115.52
BRGMII_TXD3: JP2.A10 U11.26 | length 1456.6
  Top w5: v1(1070,-375) 1055,-360 1040,-360 1035,-365 1035,-377.25 ccw(c1040.25,-377.25) 1040.25,-382.5 1052.38,-382.5 cw(c1052.38,-387.75) 1057.63,-387.75 1057.63,-392.25 cw(c1052.38,-392.25) 1052.38,-397.5 982.25,-397.5 ccw(c982.25,-402.75) 977,-402.75 977,-407.25 ccw(c982.25,-407.25) 982.25,-412.5 1029.75,-412.5 cw(c1029.75,-417.75) 1035,-417.75 1035,-435 1119.02,-519.02 1119.02,-800.84 1128.15,-809.97 U11.26@1148.19,-809.97
  Bottom w5: v1(1070,-375) 1070,-290 1100,-260 1445,-260 1460,-245 1460,-177.75 ccw(c1454.75,-177.75) 1454.75,-172.5 1447.25,-172.5 cw(c1447.25,-167.25) 1442,-167.25 1442,-162.75 cw(c1447.25,-162.75) 1447.25,-157.5 1472.75,-157.5 ccw(c1472.75,-152.25) 1478,-152.25 1478,-147.75 ccw(c1472.75,-147.75) 1472.75,-142.5 1465.25,-142.5 cw(c1465.25,-137.25) 1460,-137.25 1460,-100 1450,-90 1435.37,-90 JP2.A10@1409.84,-115.52
BRGMII_TXEN: JP2.A12 U11.27 | length 1468
  Top w5: v1(1025,-455) 1040.86,-455 1108.15,-522.29 1108.15,-808.15 1125.72,-825.72 U11.27@1148.19,-825.72
  Bottom w5: v1(1025,-455) 1025,-440 965,-380 965,-200 1005,-160 1245,-160 1260,-145 1260,-100 1290,-70 1564.32,-70 JP2.A12@1609.84,-115.52
C3.3V: B1.2 C20.2 Y1.4 | length 237
  Top w15: Y1.4@6194.61,-849.69 6270,-925.09 6270,-1000 B1.2@6325.47,-1000
C3V3A: B11.1 C109.1 C110.1 C111.1 U14.6 U14.41 | length 520.6
  Top w8: U14.41@8999.77,-881.81 8999.77,-904.77 v1(9015,-920) ; U14.6@9138.35,-774.72 9190.28,-774.72 v1(9195,-770)
  Bottom w8: v1(9015,-920) 9035,-940 C109.1@9035,-945
  Bottom w10: C110.1@9162.55,-772.22 9192.78,-772.22 v1(9195,-770) ; C110.1@9162.92,-771.85 C110.1@9162.92,-766.85
  Bottom w15: B11.1@8974.53,-980 8985,-980 9012.5,-952.5 C109.1@9027.5,-952.5 ; C109.1@9035.47,-945.47 C111.1@9095,-945.47 9129.53,-945.47 9162.55,-912.45 C110.1@9162.55,-772.22 C110.1@9162.92,-771.85
C3V3D: B9.2 B11.2 C99.1 C100.1 C101.1 C102.1 C123.1 C124.1 R154.1 R157.1 R162.1 R166.2 R167.1 R168.2 R170.2 R172.2 R173.2 R174.2 R179.2 R183.2 R185.2 R188.2 R191.2 R415.2 R416.2 R417.2 U14.15 U14.21 U14.37 U15.2 U15.4 | length 3894
  Top w8: R191.2@8870,-405 8845,-430 8845,-465 8880,-500 8880,-505 ; v2(8875,-990) 8890,-1005 R168.2@8915,-1005 ; v1(8880,-545) 8880,-505 ; R166.2@8910,-500 8885,-500 8880,-505 ; v1(8915,-905) 8930,-905 8936.78,-898.22 U14.37@8936.78,-881.81 ; v1(8975,-610) 8984.02,-619.02 U14.21@8984.02,-651.89 ; U14.15@9077.55,-650.93 v1@9077.55,-585 ; R185.2@9095,-500 9095,-490 9072.5,-467.5 9072.5,-427.5 R179.2@9095,-405
  Top w10: R191.2@8870,-405 8870,-395 v1(8885,-380) ; R188.2@9035,-405 v1(9035,-385) ; v1(9040,-1155) 9040,-1175 9085,-1220 9125,-1220 9135,-1230 9135,-1255 9230,-1350 R157.1@9235,-1350 ; R179.2@9095,-405 v1(9095,-385)
  Top w12: v1(8615,-785) 8615,-820 8625,-830 R174.2@8645,-830 ; v1(8620,-705) R173.2@8645,-705 R154.1@8645,-665
  Top w15: v1(8880,-545) 8880,-560 8905,-585 8950,-585 v1(8975,-610)
  Top w18: v1(8830,-905) v1(8915,-905)
  Top w24: C124.1@8445,-905.47 8459.53,-905.47 v2(8495,-870) ; C102.1@8480,-834.53 8480,-855 v2(8495,-870) ; C123.1@8505,-905 8495,-895 v2(8495,-870) ; v2(8620,-870) R183.2@8645,-870 ; R174.2@8645,-830 R183.2@8645,-870 ; v2(8875,-990) 8681.77,-990 8645,-953.23 R170.2@8645,-910 R183.2@8645,-870
  Top w30: U15.4@8400,-805 8400,-860.47 C124.1@8445,-905.47
  Top w32: R167.1@8065,-805 8105,-765 U15.2@8155,-765
  Bottom w8: v1(8915,-905) C99.1@8940,-905
  Bottom w10: v1(8885,-380) 8890,-385 v1(9035,-385) v1(9095,-385) ; B9.2@8915.47,-1040 8915.47,-1045.47 8945,-1075 9020,-1075 9040,-1095 v1(9040,-1155)
  Bottom w12: R417.2@8320,-535 8320,-565 8340,-585 8405,-585 ; R415.2@8445,-535 R416.2@8405,-535 8405,-585 ; v2(8495,-870) 8500,-865 8500,-630 8455,-585 8405,-585 ; v1@8612.5,-782.5 8620,-775 v1(8620,-705) ; C101.1@9075,-612.32 9077.55,-609.77 v1(9077.55,-590)
  Bottom w15: v1(8830,-905) 8810,-885 8810,-595 8860,-545 v1(8880,-545) ; C100.1@8988.39,-612.32 C101.1@9075,-612.32
  Bottom w18: v1(8915,-905) 8915,-969.53 B11.2@8915.47,-970 B9.2@8915.47,-1040
  Bottom w24: v2(8495,-870) v2(8620,-870) ; v2(8875,-990) 8895.47,-990
C5V: C125.1 C126.1 Q11.3 R167.2 R169.1 U15.3 | length 417.6
  Top w30: R169.1@7745,-825 7815,-825 7855,-865 R167.2@8065,-865 U15.3@8146,-865
C_MCLK: JP3.A3 R180.1 | length 997.8
  Top w5: JP3.A3@8465.75,-115.52 8511.27,-70 8600,-70 8615,-85 8615,-145 8595,-165 8540,-165 8520,-185 8520,-365 8590,-435 8590,-715.86 8619.14,-745 R180.1@8645,-745 8620,-745
C_MDIO: JP3.A4 R182.1 | length 748.5
  Top w5: JP3.A4@8565.75,-115.52 8510,-171.27 8510,-369.14 8580,-439.14 8580,-720 R182.1@8645,-785
C_MX1_N: J3.8 T3.22 | length 6562
  Top w6: v1(4275,-2045) 4287,-2057 9488,-2057 9669,-1876 9669,-1560.44 9890,-1339.44 9890,-1325 9878.15,-1313.15 T3.22@9878.15,-1280.8 T3.22@9875,-1283.95
  Bottom w6: J3.8@4230,-1671.65 4230,-1705 4275,-1750 v1(4275,-2045)
C_MX1_P: J3.7 T3.23 | length 6572.5
  Top w6: v1(4250,-2035) 4250,-2048 4270,-2068 9492.56,-2068 9680,-1880.56 9680,-1565 9928.15,-1316.85 T3.23@9928.15,-1280.8
  Bottom w6: J3.7@4230,-1771.65 4235.65,-1771.65 4264,-1800 4264,-1821 4255,-1830 4235,-1830 4230,-1835 4230,-1850 4235,-1855 4260,-1855 4264,-1859 4264,-2021 v1(4250,-2035)
C_MX2_N: J3.6 T3.19 | length 6569.9
  Top w6: v1(4175,-1975) 4186,-1986 4607,-1986 4640,-2019 9441,-2019 9605,-1855 9605,-1545 9744.72,-1405.28 9744.72,-1329.72 9728.15,-1313.15 T3.19@9728.15,-1280.8
  Top w8: T3.19@9728.15,-1313.15 T3.19@9728.15,-1280.8
  Bottom w6: J3.6@4130,-1671.65 4185,-1726.65 4185,-1840 4179,-1846 4145,-1846 4140,-1851 4140,-1860 4144,-1864 4149.56,-1864 4175,-1889.44 v1(4175,-1975)
C_MX2_P: J3.5 T3.20 | length 6559.8
  Top w6: v1(4155,-1990) 4162,-1997 4602.44,-1997 4635.44,-2030 9445.56,-2030 9616,-1859.56 9616,-1549.56 9755.72,-1409.83 9755.72,-1334.28 9778.15,-1311.85 T3.20@9778.15,-1280.8
  Bottom w6: J3.5@4130.65,-1771.65 J3.5@4130,-1771.65 4131.65,-1770 4164,-1770 4174,-1780 4174,-1830.44 4169.44,-1835 4115,-1835 4105,-1845 4105,-1865 4115,-1875 4145,-1875 4164,-1894 4164,-1956 4155,-1965 v1(4155,-1990)
C_MX3_N: J3.2 T3.16 | length 6628.8
  Top w6: J3.2@3930,-1671.65 3975,-1716.65 3975,-1870 4030,-1925 4607,-1925 4665,-1983 9387,-1983 9545,-1825 9545,-1500 9595,-1450 9595,-1395 9585,-1385 9530.44,-1385 9519,-1373.56 9519,-1351.44 9525.44,-1345 9590,-1345 9595,-1340 9595,-1330 9578.15,-1313.15 T3.16@9578.15,-1280.8 T3.16@9580,-1282.65
  Top w8: T3.16@9578.15,-1303.15 T3.16@9578.15,-1280.8
C_MX3_P: J3.1 T3.17 | length 6561.7
  Top w6: J3.1@3930,-1771.65 3963.35,-1805 3963.35,-1873.9 4025.44,-1936 4602.44,-1936 4660.44,-1994 9391.56,-1994 9556,-1829.56 9556,-1504.56 9606,-1454.56 9606,-1390.44 9589.56,-1374 9535,-1374 9530,-1369 9530,-1360 9534,-1356 9594.56,-1356 9606,-1344.56 9606,-1335 9628.15,-1312.85 T3.17@9628.15,-1280.8
  Top w8: T3.17@9628.15,-1306.85 T3.17@9628.15,-1280.8
C_MX4_N: J3.4 T3.13 | length 6586.4
  Top w6: J3.4@4030,-1671.65 4080,-1721.65 4080,-1860 4103.56,-1883.56 4673.56,-1883.56 4740,-1950 9340,-1950 9449,-1841 9449,-1494 9445,-1490 9400,-1490 9385,-1475 9385,-1460 9396,-1449 9505.44,-1449 9509,-1445.44 9509,-1425 9499,-1415 9380,-1415 9370,-1405 9370,-1380 9385,-1365 9434,-1365 9449,-1350 9449,-1329 9428.15,-1308.15 T3.13@9428.15,-1280.8
C_MX4_P: J3.3 T3.14 | length 6529.3
  Top w6: J3.3@4030,-1771.65 4045.65,-1771.65 4069,-1795 4069,-1864.56 4099,-1894.56 4669,-1894.56 4735.44,-1961 9344.56,-1961 9460,-1845.56 9460,-1489.44 9449.56,-1479 9404.56,-1479 9396,-1470.44 9396,-1464.56 9400.56,-1460 9510,-1460 9520,-1450 9520,-1415 9509,-1404 9385,-1404 9381,-1400 9381,-1384.56 9389.56,-1376 9438.56,-1376 9460,-1354.56 9460,-1326.85 9478.15,-1308.7 T3.14@9478.15,-1280.8
C_TD1_N: C114.2 T3.3 U14.10 | length 1121.8
  Top w6: U14.10@9138.35,-711.73 9163.83,-711.73 9236,-639.56 9236,-594.56 9360.56,-470 9794.44,-470 9894,-569.56 9894,-601 9878.6,-616.4 T3.3@9878.6,-643.2
  Top w8: v1@9878.15,-708.15 v1(9880,-710) ; T3.3@9879.94,-620 9878.6,-643.2 T3.3@9878.15,-650.88 T3.3@9880,-652.73
  Top w10: v1@9878.15,-708.15 T3.3@9878.15,-650.88
  Bottom w10: v1(9880,-710) C114.2@9880,-685
C_TD1_P: C120.2 T3.2 U14.11 | length 1134.2
  Top w6: U14.11@9138.35,-695.98 9164.02,-695.98 9225,-635 9225,-590 9356,-459 9799,-459 9875,-535 ccw(c9879.24,-530.76) 9883.49,-535 cw(c9887.73,-539.24) 9891.97,-535 cw(c9887.73,-539.24) 9891.97,-543.49 ccw(c9896.21,-547.73) 9891.97,-551.97 9905,-565 9905,-600 9928.15,-623.15 T3.2@9928.15,-640 ; v1@9928.15,-708.15 v1(9930,-710)
  Top w8: U14.11@9138.35,-695.98 9154.26,-695.98
  Top w10: v1@9928.15,-708.15 T3.2@9928.15,-650.88
  Bottom w10: v1(9930,-710) C120.2@9930,-685
C_TD2_N: C118.2 T3.6 U14.7 | length 1122.9
  Top w6: U14.7@9138.35,-758.98 9181.58,-758.98 9275,-665.56 9275,-615.56 9375.56,-515 9700,-515 9725,-540 9745,-540 9770,-515 9790,-515 9829,-554 9829,-565 9825,-569 9756,-569 9750,-575 9750,-600 9730,-620 T3.6@9730,-652.73
  Top w8: T3.6@9728.15,-650.88 T3.6@9730,-652.73
  Top w10: v1(9730,-710) T3.6@9730,-652.73
  Bottom w10: v1(9730,-710) C118.2@9730,-685
C_TD2_P: C119.2 T3.5 U14.8 | length 1142
  Top w6: U14.8@9138.35,-743.23 9181.77,-743.23 9264,-661 9264,-611 9371,-504 9704.56,-504 9729.56,-529 9740.44,-529 9765.44,-504 9794.56,-504 9840,-549.44 9840,-575 9835,-580 9765,-580 9761,-584 9761,-601 9780,-620 T3.5@9780,-652.73 ; v1@9778.15,-708.15 v1(9780,-710)
  Top w8: T3.5@9778.15,-650.88 T3.5@9780,-652.73
  Top w10: v1@9778.15,-708.15 T3.5@9778.15,-650.88
  Bottom w10: v1(9780,-710) C119.2@9780,-685
C_TD3_N: C116.2 T3.9 U14.4 | length 1136.5
  Top w6: U14.4@9138.35,-806.22 9283.78,-806.22 9294.56,-795.44 9294.56,-768.56 9270,-744 9270,-731 9275,-726 9308.56,-726 9325,-709.56 9325,-675.44 9311,-661.44 9311,-629.56 9390.56,-550 9505,-550 9535,-580 9570,-580 9600,-550 9684.44,-550 9694,-559.56 9694,-573 9690,-577 9607.17,-577 9594.72,-589.44 9594.72,-605.28 ; v1@9578.15,-708.15 v1(9580,-710) ; T3.9@9580,-652.73 9580,-620 9594.72,-605.28 ; 9593.82,-604.37 9594.72,-605.28
  Top w8: T3.9@9578.15,-621.85 T3.9@9578.15,-650.88 T3.9@9580,-652.73
  Top w10: v1@9578.15,-708.15 T3.9@9578.15,-650.88
  Bottom w10: v1(9580,-710) C116.2@9580,-685
C_TD3_P: C117.2 T3.8 U14.5 | length 1156.3
  Top w6: U14.5@9138.35,-790.47 9273.09,-790.47 9283.56,-780 9283.56,-773.56 9259,-749 9259,-721.44 9265.44,-715 9304,-715 9314,-705 9314,-680 9300,-666 9300,-625 9386,-539 9509.56,-539 9539.56,-569 9565.44,-569 9595.44,-539 9689,-539 9705,-555 9705,-580 9697,-588 9611.72,-588 9605.72,-594 9605.72,-600.72 T3.8@9628.15,-623.15 ; T3.8@9630,-652.73 T3.8@9630,-618.15
  Top w8: v1@9628.15,-708.15 v1(9630,-710) ; T3.8@9628.15,-623.15 T3.8@9628.15,-650.88 T3.8@9630,-652.73
  Top w10: v1@9628.15,-708.15 T3.8@9628.15,-650.88
  Bottom w10: v1(9630,-710) C117.2@9630,-685
C_TD4_N: C113.2 T3.12 U14.1 | length 1130.1
  Top w6: U14.1@9138.35,-853.46 9183.46,-853.46 9186.91,-856.91 9263.65,-856.91 9283.91,-836.64 9484.56,-836.64 9491,-830.2 9491,-796.44 9484.56,-790 9375,-790 9370,-785 9370,-775 9375,-770 9480,-770 9491.44,-758.56 9491.44,-741.89 9479.56,-730 9385,-730 9370,-715 9370,-630.56 9405.56,-595 9435,-595 9440,-600 9440,-630 T3.12@9430,-640 ; v1@9428.15,-708.15 v1(9430,-710)
  Top w8: U14.1@9138.35,-853.46 9156.01,-853.46
  Top w10: v1@9428.15,-708.15 T3.12@9428.15,-650.88
  Bottom w10: v1(9430,-710) C113.2@9430,-685
C_TD4_P: C115.2 T3.11 U14.2 | length 1157.7
  Top w6: U14.2@9138.35,-837.72 9187.72,-837.72 9195,-845 9260,-845 9279.36,-825.64 9474.36,-825.64 9480,-820 9480,-805 9476,-801 9366,-801 9359,-794 9359,-765.44 9365.44,-759 9475.44,-759 9480.44,-754 9480.44,-746.44 9475,-741 9380.44,-741 9358.09,-718.65 9358.09,-626.91 9401,-584 9443,-584 9478.15,-619.15 T3.11@9478.15,-650.88
  Top w8: v1@9478.15,-708.15 v1(9480,-710) ; T3.11@9480,-652.73 T3.11@9478.15,-650.88 T3.11@9480,-649.03
  Top w10: v1@9478.15,-708.15 T3.11@9478.15,-650.88
  Bottom w10: v1(9480,-710) C115.2@9480,-685
CEPHY_CLK: JP3.A13 R156.1 | length 2611.2
  Top w8: R156.1@9005,-1005 8970,-1040 8669.54,-1040 8572,-942.46 8572,-772 8540,-740 8540,-480 8415,-355 8415,-60 8500,25 9379.91,25 9465.75,-60.84 JP3.A13@9465.75,-115.13
CEPHY_RSTN: JP3.A5 R155.1 | length 547.1
  Top w5: R155.1@8645,-625 8610,-590 8610,-171.27 JP3.A5@8665.75,-115.52
CGE0_ENREG: R168.1 U14.38 | length 98.7
  Top w5: R168.1@8915,-965 8915,-940 8952.52,-902.48 U14.38@8952.52,-881.81
CGE0_INT_N: R166.1 U14.20 | length 174.9
  Top w5: R166.1@8910,-540 8935,-565 8955,-565 8999.77,-609.77 U14.20@8999.77,-651.89 U14.20@8999.77,-637.78
CGE0_LED0: R163.1 R164.1 R172.1 U14.34 | length 834
  Top w5: v1(8795,-955) 8803.5,-946.5 8803.5,-892.36 8815,-880.86 8815,-835 8828.03,-821.97 U14.34@8908.43,-821.97 ; v1(8840,-1075) 8851.5,-1086.5 8883.5,-1086.5 8890,-1080 8995,-1080 9023.5,-1108.5 9023.5,-1185 R172.1@9098.5,-1260 ; R172.1@9110,-1260 R164.1@9110,-1310 R163.1@9150,-1310
  Bottom w5: v1@8800,-960 8800,-1015 8840,-1055 v1(8840,-1075)
CGE0_LED1: R158.1 R159.1 R175.1 U14.35 | length 828.2
  Top w5: 8813.5,-953.5 8813.5,-896.5 8825,-885 8825,-840 8827.28,-837.72 U14.35@8908.43,-837.72 ; v1(8870,-1070) 9000.86,-1070 9060,-1129.14 9060,-1165 9085,-1190 9180,-1190 9190,-1200 R175.1@9190,-1220 R159.1@9270,-1220
  Bottom w5: v1(8820,-960) 8820,-1020 v1(8870,-1070)
CGE0_LED2: R183.1 R184.1 U14.32 | length 283.9
  Top w5: R183.1@8690,-870 R183.1@8685,-870 8765,-870 R184.1@8770,-865 ; R184.1@8775,-865 R184.1@8770,-865 ; U14.32@8908.43,-790.47 8814.53,-790.47 8795,-810 8795,-840 R184.1@8770,-865
CGE0_PME: R170.1 R171.1 U14.33 | length 299.1
  Top w5: R170.1@8685,-910 R171.1@8730,-910 8770.86,-910 8805,-875.86 8805,-820 8818.78,-806.22 U14.33@8908.43,-806.22
CGE0_RXCLK: R147.2 U14.19 | length 139
  Top w5: R147.2@8950,-540 8950,-545.86 9015.52,-611.38 U14.19@9015.52,-651.89
CGE0_RXCTL: R148.2 R176.1 U14.13 | length 560.8
  Top w5: U14.13@9110,-651.89 9110,-640 9114,-636 9154,-636 9171.5,-618.5 9171.81,-618.5 9188.93,-601.38 9188.93,-539.5 cw(c9193.43,-539.5) 9193.43,-535 9229.43,-535 ccw(c9229.43,-530.5) 9233.93,-530.5 9233.93,-529.5 ccw(c9229.43,-529.5) 9229.43,-525 9193.43,-525 cw(c9193.43,-520.5) 9188.93,-520.5 9188.93,-519.5 cw(c9193.43,-519.5) 9193.43,-515 9229.43,-515 ccw(c9229.43,-510.5) 9233.93,-510.5 9233.93,-509.5 ccw(c9229.43,-509.5) 9229.43,-505 9193.43,-505 cw(c9193.43,-500.5) 9188.93,-500.5 9188.93,-499.5 cw(c9193.43,-499.5) 9193.43,-495 9229.43,-495 ccw(c9229.43,-490.5) 9233.93,-490.5 9233.93,-489.5 ccw(c9229.43,-489.5) 9229.43,-485 9193.43,-485 cw(c9193.43,-480.5) 9188.93,-480.5 9188.93,-471.07 R176.1@9215,-445 R148.2@9255,-445
CGE0_RXD0: R149.2 R179.1 R181.1 U14.14 | length 350.4
  Top w5: U14.14@9094.26,-651.89 9094.26,-633.29 9102.55,-625 9149.44,-625 9166.94,-607.5 9167.25,-607.5 9177.93,-596.82 9177.93,-447.93 R181.1@9175,-445 R179.1@9095,-445
CGE0_RXD1: R150.2 R185.1 R187.1 U14.16 | length 233.6
  Top w5: R150.2@9057.55,-542.55 R150.2@9055,-540 ; U14.16@9062.76,-651.89 9062.76,-612.76 9025,-575 9025,-560 9030,-555.02 9050,-535 R150.2@9055,-540 ; R187.1@9135,-540 R185.1@9095,-540 R150.2@9055,-540
CGE0_RXD2: R151.2 R188.1 R190.1 U14.17 | length 270.5
  Top w5: R151.2@8995,-445 R188.1@9030,-445 ; R188.1@9035,-445 R188.1@9030,-445 ; U14.17@9047.01,-651.89 9047.01,-612.57 9010,-575.56 R190.1@9010,-540 9030,-520 R188.1@9030,-445
CGE0_RXD3: R153.2 R191.1 R192.1 U14.18 | length 320.5
  Top w5: R191.1@8870,-445 R153.2@8950,-445 8950,-450 8980,-480 8980,-561.72 9031.26,-612.98 U14.18@9031.26,-651.89
CMAC_MDC: C127.2 R173.1 R180.2 U14.30 | length 269.2
  Top w5: R173.1@8685,-705 R180.2@8685,-745 C127.2@8730,-745 8743.98,-758.98 U14.30@8908.43,-758.98
CMAC_MDIO: C128.2 R174.1 R182.2 U14.31 | length 272.7
  Top w5: R174.1@8685,-830 R182.2@8685,-785 C128.2@8730,-785 8740.28,-774.72 U14.31@8908.43,-774.72
CON12VA: C1.1 C2.1 C7.1 C300.1 PWR1.1 PWR1.2 PWR1.3 R1.1 U1.1 U1.2 U1.3 U3.7 | length 2669.7
  Top w12: C2.1@10755,-525 10755,-580 10765.64,-590.64 U3.7@10818.26,-590.64 10884.36,-590.64 C7.1@10885,-590
  Top w15: PWR1.3@10462.87,-1968.76 PWR1.2@10659.72,-1968.76 PWR1.1@10955,-1968.76 11058.76,-1865 R1.1@11199.69,-1865 11185,-1850.32 11185,-1805 ; U1.1@10805,-870 U1.2@10805,-820 ; U1.3@10805,-770 U1.2@10805,-820 ; C7.1@10885,-590 10976.1,-681.1 10976.1,-820 ; 11185,-1828.76 11185,-1805 ; U1.2@10805,-820 10976.1,-820 ; 10976.1,-820 10976.1,-970 10976.1,-1276.1 11185,-1485 11185,-1805
CON12VB: C5.1 C6.1 C8.1 C301.1 PWR2.1 PWR2.2 PWR2.3 R4.1 U2.1 U2.2 U2.3 U4.7 | length 1680.7
  Top w5: U2.3@10500,-1165 C6.1@10671.1,-1165
  Top w12: C5.1@10465,-925 10465,-965 10490.64,-990.64 10585.64,-990.64 C8.1@10590,-995
  Top w15: PWR2.3@10462.87,-1622.31 PWR2.2@10659.72,-1622.31 ; C8.1@10595,-990 10635,-990 10671.1,-1026.1 C6.1@10671.1,-1135 10671.1,-1165 10671.1,-1319.21 R4.1@10630.32,-1360 C301.1@10735,-1360 10735,-1547.03 PWR2.2@10659.72,-1622.31 ; PWR2.1@10955,-1622.31 PWR2.2@10659.72,-1622.31
CPHY105: B10.1 C103.1 C104.1 C105.1 U14.3 U14.9 U14.40 | length 664
  Top w8: U14.40@8984.02,-881.81 8984.02,-924.02 v1(8990,-930) ; U14.9@9138.35,-727.48 9172.52,-727.48 v1(9175,-725)
  Top w10: U14.3@9138.35,-821.97 9199.52,-821.97 v1(9202.55,-825)
  Top w12: v1(9140,-895) B10.1@9225.47,-895
  Bottom w8: C105.1@8980,-909.51 8980,-910 C105.1@8985,-905 8985,-925 v1(8990,-930) ; v1(9175,-725) C103.1@9200,-725
  Bottom w10: C103.1@9200,-725 9225,-750 C104.1@9225,-825 v1(9202.55,-825)
  Bottom w12: C105.1@8985,-905 8995,-895 v1(9140,-895)
  Bottom w15: v1(9195,-895) 9202.55,-887.45 v1(9202.55,-825)
CRGMII_RXCK: JP3.C11 R147.1 | length 617.6
  Top w5: R147.1@8950,-500 v1(8950,-475)
  Bottom w5: v1(8950,-475) 8950,-430 8975,-405 9202,-405 cw(c9202,-413) 9210,-413 9210,-427 ccw(c9218,-427) 9218,-435 9222,-435 ccw(c9222,-427) 9230,-427 9230,-383 cw(c9238,-383) 9238,-375 9242,-375 cw(c9242,-383) 9250,-383 9250,-397 ccw(c9258,-397) 9258,-405 9280,-405 9295,-390 9295,-344.78 JP3.C11@9265.75,-315.52
CRGMII_RXD0: JP3.C7 R149.1 | length 412.6
  Top w5: JP3.C7@8865.75,-315.52 8916.27,-265 9105,-265 9115,-275 9115,-350 9135,-370 R149.1@9135,-405
CRGMII_RXD1: JP3.C8 R150.1 | length 395.6
  Top w5: JP3.C8@8965.75,-315.52 8965.75,-305.25 8985,-286 9011,-286 9022.52,-297.52 9022.52,-337.52 9040.02,-355.02 9099.98,-355.02 9104.95,-360 9104.95,-364.95 9102.41,-367.5 9057.5,-367.5 9055,-370 9055,-380 9060,-385 R150.1@9060,-495
CRGMII_RXD2: JP3.C9 R151.1 | length 490.7
  Top w5: 8972.72,-371.42 cw(c8967.07,-365.76) 8961.42,-371.42 8920,-330 8920,-295 8940,-275 9095,-275 9105,-285 9105,-310 9099.48,-315.52 JP3.C9@9065.75,-315.52 ; 8972.73,-371.41 8996.14,-348 cw(c9001.79,-353.66) 9007.45,-348 9010.28,-350.83 cw(c9004.62,-356.49) 9010.29,-362.14 8985,-387.43 ccw(c8988.79,-391.21) 8985,-395 R151.1@8995,-405
CRGMII_RXD3: JP3.C10 R153.1 | length 447.5
  Top w5: v1@8925,-360 v1(8925,-365) 8950,-390 ; 8940,-380 8950,-390 ; R153.1@8950,-405 8950,-390
  Bottom w5: v1@8925,-360 8927.5,-362.5 8930,-365 9205,-365 9215,-355 9215,-330 9201.27,-316.27 9165,-316.27 JP3.C10@9165.75,-315.52
CRGMII_RXDV: JP3.C12 R148.1 | length 209.9
  Top w5: R148.1@9255,-405 9355,-405 9385,-375 9385,-334.78 JP3.C12@9365.75,-315.52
